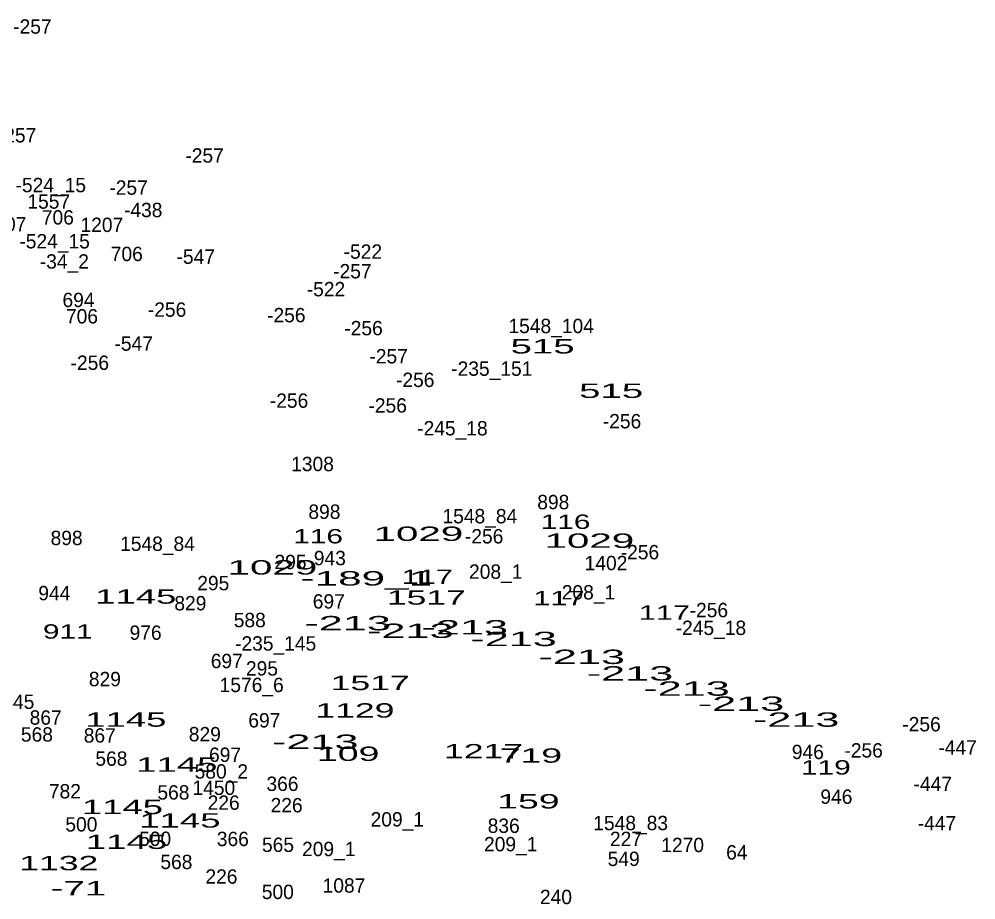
# Model space of a CAD drawing. Extents: x -660434 to -656144, y -997850 to -994016.
# Drawn here: x -659029.2 to -658762.7, y -994753.9 to -994508.4 of the extents above; entities that cross this region are included whole.
import ezdxf
from ezdxf.enums import TextEntityAlignment as Align

# ---------------------------------------------------------------- set-up
doc = ezdxf.new("R2010")
doc.units = 0
doc.header["$LTSCALE"] = 1.6
doc.layers.add('24', color=7, linetype='Continuous')

msp = doc.modelspace()

# ---------------------------------------------------------------- texts
at = {"layer": '24'}
for s, p in [('-257', (-659025.531, -994512.5)), ('-257', (-659029.801, -994542.8)), ('-257', (-658977.571, -994548.43)), ('-524_15', (-659020.409, -994556.67)), ('-257', (-658998.741, -994557.37)), ('1557', (-659020.976, -994561.26)), ('-438', (-658994.669, -994563.62)), ('706', (-659018.442, -994565.68)), ('1207', (-659033.17, -994567.58)), ('1207', (-659006.19, -994567.76)), ('-524_15', (-659019.349, -994572.33)), ('-522', (-658933.485, -994575.21)), ('706', (-658999.242, -994575.86)), ('-547', (-658980.035, -994576.63)), ('-34_2', (-659016.637, -994577.96)), ('-257', (-658936.411, -994580.68)), ('-522', (-658943.765, -994585.68)), ('694', (-659012.693, -994588.68)), ('706', (-659011.722, -994593.24)), ('-256', (-658988.03, -994591.38)), ('-256', (-658954.81, -994592.92)), ('-256', (-658933.3, -994596.54)), ('1548_104', (-658881.034, -994595.94)), ('-547', (-658997.315, -994600.83)), ('-257', (-658926.311, -994604.37)), ('-256', (-659009.54, -994606.18)), ('-235_151', (-658897.569, -994607.83)), ('-256', (-658918.9, -994610.95)), ('-256', (-658954.05, -994616.74)), ('-256', (-658926.58, -994618.08)), ('-256', (-658861.3, -994622.47)), ('-245_18', (-658908.539, -994624.44)), ('1308', (-658947.504, -994634.4)), ('898', (-658880.443, -994645.01)), ('898', (-658944.193, -994647.7)), ('1548_84', (-658900.897, -994648.94)), ('898', (-659016.003, -994655)), ('-256', (-658899.7, -994654.54)), ('1548_84', (-658990.687, -994656.62)), ('-256', (-658856.31, -994658.96)), ('295', (-658953.643, -994661.7)), ('943', (-658942.687, -994660.61)), ('1402', (-658865.758, -994661.99)), ('208_1', (-658896.473, -994664.39)), ('295', (-658975.153, -994667.59)), ('944', (-659019.421, -994670.37)), ('208_1', (-658870.643, -994670.15)), ('829', (-658981.533, -994673.19)), ('697', (-658942.973, -994672.68)), ('-256', (-658837.11, -994675.1)), ('588', (-658964.987, -994677.88)), ('976', (-658994.003, -994681.39)), ('-245_18', (-658836.539, -994680.05)), ('-235_145', (-658957.779, -994684.4)), ('697', (-658971.393, -994689.29)), ('295', (-658961.593, -994691.36)), ('829', (-659005.343, -994694.32)), ('1576_6', (-658964.455, -994695.96)), ('1445', (-659030.939, -994700.65)), ('867', (-659021.838, -994705.04)), ('697', (-658960.923, -994705.81)), ('-256', (-658777.87, -994706.9)), ('568', (-659024.273, -994709.76)), ('867', (-659006.768, -994710.03)), ('829', (-658977.503, -994709.68)), ('-447', (-658767.819, -994713.37)), ('568', (-659003.533, -994716.49)), ('697', (-658971.873, -994715.41)), ('946', (-658809.543, -994714.62)), ('-256', (-658794, -994714.19)), ('580_2', (-658972.909, -994720.06)), ('366', (-658955.878, -994723.51)), ('-447', (-658774.729, -994723.55)), ('782', (-659016.483, -994725.58)), ('568', (-658986.253, -994725.9)), ('1450', (-658974.998, -994724.62)), ('946', (-658801.583, -994727.1)), ('226', (-658972.253, -994728.76)), ('226', (-658954.723, -994729.47)), ('500', (-659011.895, -994734.81)), ('209_1', (-658923.888, -994733.41)), ('1548_83', (-658858.892, -994734.44)), ('-447', (-658773.579, -994734.5)), ('836', (-658894.253, -994735.19)), ('500', (-658991.355, -994738.84)), ('366', (-658969.708, -994738.87)), ('209_1', (-658892.298, -994740.33)), ('227', (-658860.193, -994738.86)), ('565', (-658957.123, -994740.5)), ('209_1', (-658942.988, -994741.67)), ('1270', (-658844.41, -994740.56)), ('64', (-658829.317, -994742.61)), ('568', (-658985.423, -994745.28)), ('549', (-658860.837, -994744.42)), ('226', (-658972.873, -994749.35)), ('500', (-658957.175, -994753.63)), ('1087', (-658938.74, -994751.84)), ('240', (-658879.695, -994755.04))]:
    msp.add_text(s, height=4, dxfattribs=at).set_placement(p, align=Align.CENTER)
for s, width, p in [('515', 2, (-658883.427, -994601.61)), ('515', 2, (-658864.327, -994614)), ('116', 1.55, (-658877.019, -994650.48)), ('116', 1.55, (-658945.949, -994654.52)), ('1029', 2.1, (-658918.019, -994653.83)), ('1029', 2.1, (-658870.399, -994655.76)), ('1029', 2.1, (-658958.669, -994663.2)), ('-189_1', 2.2, (-658932.513, -994666.26)), ('117', 1.6, (-658915.539, -994665.81)), ('1145', 1.9, (-658996.729, -994671.32)), ('1517', 1.85, (-658915.799, -994671.59)), ('117', 1.6, (-658878.869, -994671.76)), ('117', 1.6, (-658849.489, -994675.8)), ('-213', 2.25, (-658937.731, -994678.75)), ('911', 1.55, (-659015.679, -994681.07)), ('-213', 2.25, (-658920.261, -994680.87)), ('-213', 2.25, (-658905.091, -994679.9)), ('-213', 2.25, (-658891.511, -994683.14)), ('-213', 2.25, (-658872.511, -994688.13)), ('-213', 2.25, (-658859.071, -994692.74)), ('1517', 1.85, (-658931.449, -994695.41)), ('-213', 2.25, (-658843.321, -994696.97)), ('1129', 1.85, (-658935.689, -994703.06)), ('-213', 2.25, (-658828.151, -994701.19)), ('1145', 1.9, (-658999.509, -994705.61)), ('-213', 2.25, (-658812.791, -994705.61)), ('-213', 2.25, (-658946.761, -994711.79)), ('109', 1.95, (-658937.579, -994715.14)), ('1217', 1.85, (-658899.889, -994714.43)), ('719', 1.95, (-658886.687, -994715.63)), ('1145', 1.9, (-658985.299, -994718.16)), ('119', 1.55, (-658804.519, -994718.93)), ('159', 1.95, (-658887.383, -994728.39)), ('1145', 1.9, (-659000.469, -994729.97)), ('1145', 1.9, (-658984.439, -994733.72)), ('1145', 1.9, (-658999.319, -994739.67)), ('1132', 1.85, (-659018.184, -994745.61)), ('-71', 2, (-659012.695, -994752.63))]:
    msp.add_text(s, height=4, dxfattribs=dict(at, width=width)).set_placement(p, align=Align.CENTER)

doc.saveas('drawing.dxf')
